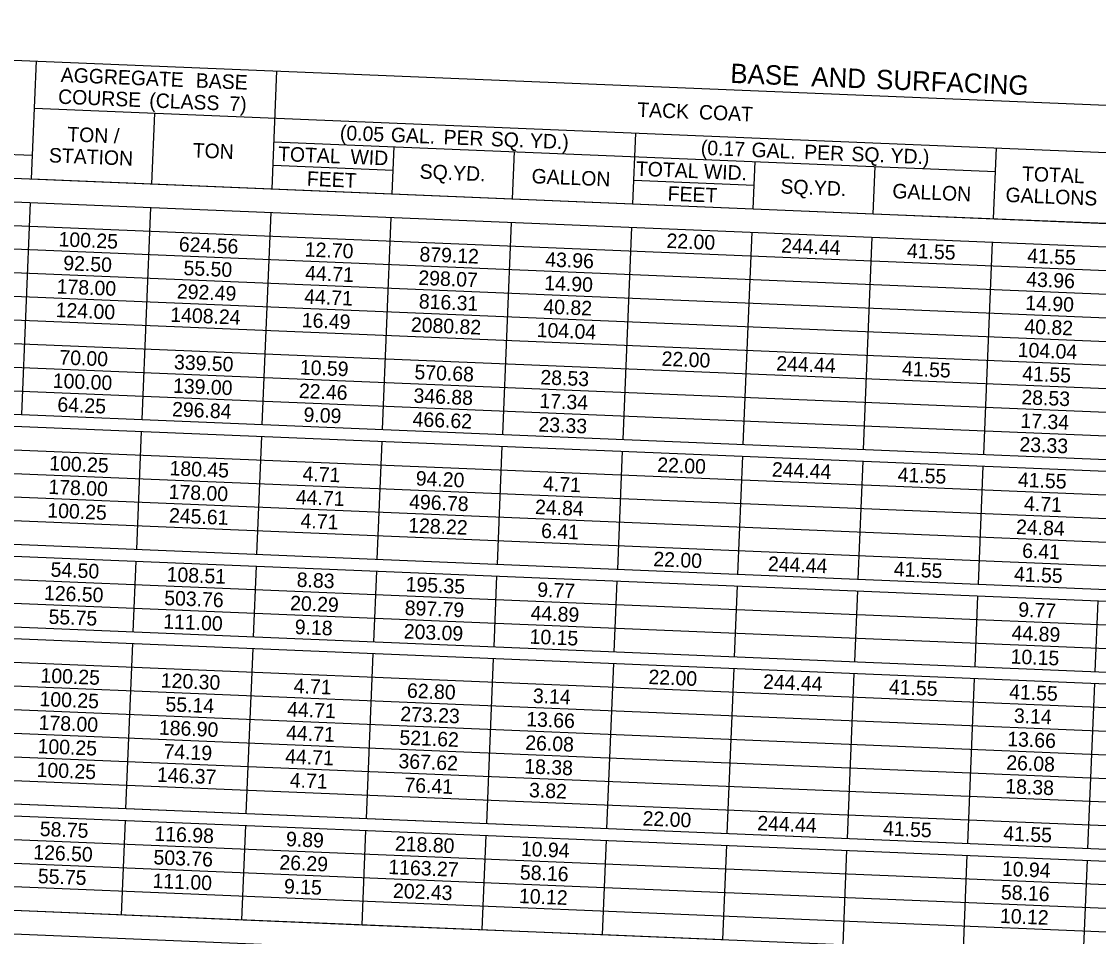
# Model space of a CAD drawing. Extents: x 1164179 to 1171425, y 1655958 to 1657208.
# Drawn here: x 1168414.3 to 1168859.2, y 1656454.9 to 1656832.9 of the extents above; entities that cross this region are included whole.
import ezdxf

# ---------------------------------------------------------------- set-up
doc = ezdxf.new("R2010")
doc.units = 0
doc.layers.add('Default', color=7, linetype='Continuous')

msp = doc.modelspace()

# ---------------------------------------------------------------- linework, layer by layer
at = {"layer": 'Default'}
for p, q in [((1168026.37, 1656832.93), (1169513.44, 1656771.41)), ((1168418.41, 1656767.92), (1168420.42, 1656816.63)), ((1168517.77, 1656763.81), (1168519.79, 1656812.52)), ((1168419.62, 1656797.14), (1169512.63, 1656751.93)), ((1168468.09, 1656765.86), (1168469.3, 1656795.09)), ((1168666.82, 1656757.64), (1168668.03, 1656786.87)), ((1168024.36, 1656784.22), (1169511.42, 1656722.7)), ((1168518.58, 1656783.29), (1168816.68, 1656770.96)), ((1168567.46, 1656761.75), (1168568.26, 1656781.24)), ((1168815.87, 1656751.48), (1168817.08, 1656780.7)), ((1168369.13, 1656779.72), (1168418.81, 1656777.66)), ((1168418.41, 1656767.92), (1168418.81, 1656777.66)), ((1168617.14, 1656759.7), (1168617.95, 1656779.18)), ((1168023.96, 1656774.48), (1169511.02, 1656712.96)), ((1168518.18, 1656773.55), (1168567.86, 1656771.49)), ((1168567.46, 1656761.75), (1168567.86, 1656771.49)), ((1168716.5, 1656755.59), (1168717.31, 1656775.07)), ((1168766.19, 1656753.53), (1168766.99, 1656773.01)), ((1168418.41, 1656767.92), (1168567.46, 1656761.75)), ((1168667.22, 1656767.38), (1168716.91, 1656765.33)), ((1168023.55, 1656764.74), (1169510.62, 1656703.22)), ((1168716.5, 1656755.59), (1168716.91, 1656765.33)), ((1168414.38, 1656670.5), (1168418.01, 1656758.18)), ((1168414.38, 1656670.5), (1168418.01, 1656758.18)), ((1168567.46, 1656761.75), (1168716.5, 1656755.59)), ((1168023.15, 1656754.99), (1169510.22, 1656693.48)), ((1168464.06, 1656668.45), (1168467.69, 1656756.12)), ((1168464.06, 1656668.45), (1168467.69, 1656756.12)), ((1168513.74, 1656666.39), (1168517.37, 1656754.07)), ((1168513.74, 1656666.39), (1168517.37, 1656754.07)), ((1168716.5, 1656755.59), (1168766.19, 1656753.53)), ((1168766.19, 1656753.53), (1168915.23, 1656747.37)), ((1168563.43, 1656664.34), (1168567.05, 1656752.01)), ((1168563.43, 1656664.34), (1168567.05, 1656752.01)), ((1168613.11, 1656662.28), (1168616.74, 1656749.96)), ((1168613.11, 1656662.28), (1168616.74, 1656749.96)), ((1168022.75, 1656745.25), (1169509.81, 1656683.74)), ((1168662.79, 1656660.23), (1168666.42, 1656747.9)), ((1168662.79, 1656660.23), (1168666.42, 1656747.9)), ((1168712.47, 1656658.17), (1168716.1, 1656745.84)), ((1168712.47, 1656658.17), (1168716.1, 1656745.84)), ((1168762.16, 1656656.11), (1168765.78, 1656743.79)), ((1168762.16, 1656656.11), (1168765.78, 1656743.79)), ((1168811.84, 1656654.06), (1168815.47, 1656741.73)), ((1168811.84, 1656654.06), (1168815.47, 1656741.73)), ((1168022.34, 1656735.51), (1169509.41, 1656673.99)), ((1168021.94, 1656725.77), (1169509.01, 1656664.25)), ((1168021.54, 1656716.03), (1169508.6, 1656654.51)), ((1168021.13, 1656706.29), (1169508.2, 1656644.77)), ((1168020.73, 1656696.54), (1169507.8, 1656635.03)), ((1168020.33, 1656686.8), (1169507.39, 1656625.29)), ((1168020.33, 1656686.8), (1169507.39, 1656625.29)), ((1168020.13, 1656681.93), (1169507.19, 1656620.41)), ((1168019.72, 1656672.19), (1169506.79, 1656610.67)), ((1168019.32, 1656662.45), (1169506.39, 1656600.93)), ((1168461.85, 1656614.87), (1168463.86, 1656663.58)), ((1168461.85, 1656614.87), (1168463.86, 1656663.58)), ((1168511.53, 1656612.81), (1168513.54, 1656661.52)), ((1168511.53, 1656612.81), (1168513.54, 1656661.52)), ((1168561.21, 1656610.76), (1168563.23, 1656659.46)), ((1168561.21, 1656610.76), (1168563.23, 1656659.46)), ((1168610.89, 1656608.7), (1168612.91, 1656657.41)), ((1168610.89, 1656608.7), (1168612.91, 1656657.41)), ((1168018.92, 1656652.71), (1169505.98, 1656591.19)), ((1168660.58, 1656606.65), (1168662.59, 1656655.35)), ((1168660.58, 1656606.65), (1168662.59, 1656655.35)), ((1168710.26, 1656604.59), (1168712.27, 1656653.3)), ((1168710.26, 1656604.59), (1168712.27, 1656653.3)), ((1168759.94, 1656602.54), (1168761.96, 1656651.24)), ((1168759.94, 1656602.54), (1168761.96, 1656651.24)), ((1168809.62, 1656600.48), (1168811.64, 1656649.19)), ((1168809.62, 1656600.48), (1168811.64, 1656649.19)), ((1168018.52, 1656642.97), (1169505.58, 1656581.45)), ((1168018.11, 1656633.22), (1169505.18, 1656571.71)), ((1168017.91, 1656628.35), (1169504.98, 1656566.84)), ((1168017.51, 1656618.61), (1169504.57, 1656557.09)), ((1168362.48, 1656618.98), (1169505.18, 1656571.71)), ((1168017.11, 1656608.87), (1169504.17, 1656547.35)), ((1168460.43, 1656580.77), (1168461.64, 1656610)), ((1168460.43, 1656580.77), (1168461.64, 1656610)), ((1168510.12, 1656578.72), (1168511.33, 1656607.94)), ((1168510.12, 1656578.72), (1168511.33, 1656607.94)), ((1168559.8, 1656576.66), (1168561.01, 1656605.89)), ((1168559.8, 1656576.66), (1168561.01, 1656605.89)), ((1168609.48, 1656574.61), (1168610.69, 1656603.83)), ((1168609.48, 1656574.61), (1168610.69, 1656603.83)), ((1168016.7, 1656599.13), (1169503.77, 1656537.61)), ((1168659.17, 1656572.55), (1168660.37, 1656601.78)), ((1168659.17, 1656572.55), (1168660.37, 1656601.78)), ((1168708.85, 1656570.49), (1168710.06, 1656599.72)), ((1168708.85, 1656570.49), (1168710.06, 1656599.72)), ((1168016.5, 1656594.26), (1169503.57, 1656532.74)), ((1168758.53, 1656568.44), (1168759.74, 1656597.66)), ((1168758.53, 1656568.44), (1168759.74, 1656597.66)), ((1168808.21, 1656566.38), (1168809.42, 1656595.61)), ((1168808.21, 1656566.38), (1168809.42, 1656595.61)), ((1168857.9, 1656564.33), (1168859.1, 1656593.55)), ((1168857.9, 1656564.33), (1168859.1, 1656593.55)), ((1168016.1, 1656584.52), (1169503.16, 1656523)), ((1168361.07, 1656584.88), (1169503.77, 1656537.61)), ((1168457.41, 1656507.71), (1168460.23, 1656575.9)), ((1168457.41, 1656507.71), (1168460.23, 1656575.9)), ((1168015.69, 1656574.77), (1169502.76, 1656513.26)), ((1168507.1, 1656505.65), (1168509.92, 1656573.85)), ((1168507.1, 1656505.65), (1168509.92, 1656573.85)), ((1168556.78, 1656503.6), (1168559.6, 1656571.79)), ((1168556.78, 1656503.6), (1168559.6, 1656571.79)), ((1168606.46, 1656501.54), (1168609.28, 1656569.73)), ((1168606.46, 1656501.54), (1168609.28, 1656569.73)), ((1168656.14, 1656499.49), (1168658.96, 1656567.68)), ((1168656.14, 1656499.49), (1168658.96, 1656567.68)), ((1168015.29, 1656565.03), (1169502.36, 1656503.51)), ((1168705.83, 1656497.43), (1168708.65, 1656565.62)), ((1168705.83, 1656497.43), (1168708.65, 1656565.62)), ((1168755.51, 1656495.38), (1168758.33, 1656563.57)), ((1168755.51, 1656495.38), (1168758.33, 1656563.57)), ((1168805.19, 1656493.32), (1168808.01, 1656561.51)), ((1168805.19, 1656493.32), (1168808.01, 1656561.51)), ((1168854.87, 1656491.27), (1168857.69, 1656559.46)), ((1168854.87, 1656491.27), (1168857.69, 1656559.46)), ((1168014.89, 1656555.29), (1169501.95, 1656493.77)), ((1168014.49, 1656545.55), (1169501.55, 1656484.03)), ((1168014.08, 1656535.81), (1169501.15, 1656474.29)), ((1168013.68, 1656526.07), (1169500.75, 1656464.55)), ((1168013.48, 1656521.19), (1169500.54, 1656459.68)), ((1168013.08, 1656511.45), (1169500.14, 1656449.94)), ((1168358.05, 1656511.82), (1169500.75, 1656464.55)), ((1168012.67, 1656501.71), (1169499.74, 1656440.19)), ((1168455.6, 1656463.87), (1168457.21, 1656502.84)), ((1168455.6, 1656463.87), (1168457.21, 1656502.84)), ((1168505.28, 1656461.82), (1168506.89, 1656500.78)), ((1168505.28, 1656461.82), (1168506.89, 1656500.78)), ((1168554.96, 1656459.76), (1168556.58, 1656498.73)), ((1168554.96, 1656459.76), (1168556.58, 1656498.73)), ((1168604.65, 1656457.71), (1168606.26, 1656496.67)), ((1168604.65, 1656457.71), (1168606.26, 1656496.67)), ((1168012.27, 1656491.97), (1169499.33, 1656430.45)), ((1168654.33, 1656455.65), (1168655.94, 1656494.62)), ((1168654.33, 1656455.65), (1168655.94, 1656494.62)), ((1168704.01, 1656453.59), (1168705.62, 1656492.56)), ((1168704.01, 1656453.59), (1168705.62, 1656492.56)), ((1168753.69, 1656451.54), (1168755.31, 1656490.51)), ((1168753.69, 1656451.54), (1168755.31, 1656490.51)), ((1168803.38, 1656449.48), (1168804.99, 1656488.45)), ((1168803.38, 1656449.48), (1168804.99, 1656488.45)), ((1168011.87, 1656482.23), (1168554.96, 1656459.76)), ((1168011.87, 1656482.23), (1169498.93, 1656420.71)), ((1168853.06, 1656447.43), (1168854.67, 1656486.4)), ((1168853.06, 1656447.43), (1168854.67, 1656486.4)), ((1168011.46, 1656472.49), (1169498.53, 1656410.97)), ((1168554.96, 1656459.76), (1168654.33, 1656455.65)), ((1168654.33, 1656455.65), (1168704.01, 1656453.59))]:
    msp.add_line(p, q, dxfattribs=at)

# ---------------------------------------------------------------- texts
for s, height, p in [('AGGREGATE', 6, (1168430.39, 1656807.96)), (' BASE', 6, (1168483.96, 1656805.74)), ('BASE', 8, (1168707, 1656807.6)), (' AND', 8, (1168737.48, 1656806.34)), (' SURFACING', 8, (1168764.23, 1656805.23)), ('COURSE', 6, (1168429.3, 1656798.99)), (' (CLASS', 6, (1168464.73, 1656797.53)), (' 7)', 6, (1168497.82, 1656796.16)), ('TACK', 6, (1168668.58, 1656793.6)), (' COAT', 6, (1168691.84, 1656792.64)), ('TON', 6, (1168433.08, 1656783.45)), ('(0.05', 6, (1168545.72, 1656784.04)), (' GAL.', 6, (1168564.55, 1656783.27)), (' /', 6, (1168450.09, 1656782.75)), (' PER', 6, (1168586.31, 1656782.37)), (' SQ.', 6, (1168605.82, 1656781.56)), (' YD.)', 6, (1168622, 1656780.89)), ('STATION', 6, (1168425.5, 1656774.76)), ('TON', 6, (1168484.91, 1656776.8)), ('TOTAL', 6, (1168520.17, 1656775.34)), ('(0.17', 6, (1168694.83, 1656777.88)), (' GAL.', 6, (1168713.54, 1656777.1)), (' PER', 6, (1168735.3, 1656776.2)), (' SQ.', 6, (1168754.81, 1656775.4)), (' YD.)', 6, (1168770.99, 1656774.73)), (' WID', 6, (1168547.83, 1656774.2)), ('SQ.YD.', 6, (1168578.67, 1656768.04)), ('GALLON', 6, (1168624.91, 1656766.13)), ('TOTAL WID.', 6, (1168668.01, 1656769.23)), ('TOTAL', 6, (1168827.54, 1656767.13)), ('FEET', 6, (1168532.07, 1656765.09)), ('SQ.YD.', 6, (1168727.72, 1656761.88)), ('FEET', 6, (1168681.12, 1656758.93)), ('GALLON', 6, (1168773.96, 1656759.97)), ('GALLONS', 6, (1168820.73, 1656758.41)), ('100.25', 6, (1168429.48, 1656740.06)), ('22.00', 6, (1168680.66, 1656739.43)), ('624.56', 6, (1168479.19, 1656738.01)), ('12.70', 6, (1168531.21, 1656735.85)), ('244.44', 6, (1168728.02, 1656737.47)), ('41.55', 6, (1168779.99, 1656735.32)), ('92.50', 6, (1168431.44, 1656730.22)), ('879.12', 6, (1168578.59, 1656733.89)), ('43.96', 6, (1168630.56, 1656731.74)), ('41.55', 6, (1168829.67, 1656733.26)), ('55.50', 6, (1168481.12, 1656728.17)), ('44.71', 6, (1168531.38, 1656726.09)), ('298.07', 6, (1168578.15, 1656724.15)), ('14.90', 6, (1168630.17, 1656722)), ('43.96', 6, (1168829.29, 1656723.52)), ('178.00', 6, (1168428.71, 1656720.58)), ('292.49', 6, (1168478.38, 1656718.52)), ('44.71', 6, (1168530.97, 1656716.35)), ('816.31', 6, (1168578.33, 1656714.39)), ('40.82', 6, (1168629.79, 1656712.26)), ('14.90', 6, (1168828.9, 1656713.78)), ('124.00', 6, (1168428.31, 1656710.84)), ('1408.24', 6, (1168475.66, 1656708.88)), ('16.49', 6, (1168529.99, 1656706.63)), ('2080.82', 6, (1168575.05, 1656704.76)), ('40.82', 6, (1168828.52, 1656704.04)), ('104.04', 6, (1168627.04, 1656702.61)), ('104.04', 6, (1168825.77, 1656694.39)), ('70.00', 6, (1168429.83, 1656691.26)), ('22.00', 6, (1168678.65, 1656690.72)), ('339.50', 6, (1168477.18, 1656689.3)), ('10.59', 6, (1168529.18, 1656687.15)), ('244.44', 6, (1168726, 1656688.76)), ('41.55', 6, (1168777.98, 1656686.61)), ('100.00', 6, (1168427.1, 1656681.61)), ('570.68', 6, (1168576.53, 1656685.19)), ('28.53', 6, (1168628.55, 1656683.03)), ('41.55', 6, (1168827.66, 1656684.56)), ('139.00', 6, (1168476.78, 1656679.55)), ('22.46', 6, (1168528.78, 1656677.4)), ('346.88', 6, (1168576.13, 1656675.45)), ('17.34', 6, (1168628.16, 1656673.29)), ('28.53', 6, (1168827.28, 1656674.81)), ('64.25', 6, (1168428.99, 1656671.77)), ('296.84', 6, (1168476.38, 1656669.81)), ('9.09', 6, (1168530.7, 1656667.57)), ('466.62', 6, (1168575.76, 1656665.7)), ('23.33', 6, (1168627.74, 1656663.55)), ('17.34', 6, (1168826.89, 1656665.07)), ('23.33', 6, (1168826.47, 1656655.33)), ('100.25', 6, (1168425.65, 1656647.52)), ('180.45', 6, (1168475.34, 1656645.46)), ('22.00', 6, (1168676.83, 1656646.88)), ('4.71', 6, (1168530.28, 1656643.19)), ('94.20', 6, (1168577.06, 1656641.25)), ('244.44', 6, (1168724.19, 1656644.92)), ('41.55', 6, (1168776.16, 1656642.77)), ('178.00', 6, (1168425.29, 1656637.77)), ('4.71', 6, (1168629.64, 1656639.08)), ('41.55', 6, (1168825.85, 1656640.72)), ('178.00', 6, (1168474.97, 1656635.72)), ('44.71', 6, (1168527.55, 1656633.54)), ('100.25', 6, (1168424.85, 1656628.03)), ('496.78', 6, (1168574.32, 1656631.61)), ('24.84', 6, (1168626.35, 1656629.46)), ('4.71', 6, (1168828.37, 1656630.86)), ('245.61', 6, (1168475.13, 1656625.95)), ('4.71', 6, (1168529.47, 1656623.7)), ('128.22', 6, (1168573.95, 1656621.86)), ('6.41', 6, (1168628.84, 1656619.59)), ('24.84', 6, (1168825.08, 1656621.23)), ('6.41', 6, (1168827.57, 1656611.37)), ('22.00', 6, (1168675.22, 1656607.92)), ('244.44', 6, (1168722.58, 1656605.96)), ('54.50', 6, (1168426.2, 1656603.58)), ('108.51', 6, (1168474.13, 1656601.6)), ('41.55', 6, (1168774.55, 1656603.81)), ('41.55', 6, (1168824.23, 1656601.75)), ('8.83', 6, (1168527.88, 1656599.37)), ('195.35', 6, (1168572.89, 1656597.51)), ('126.50', 6, (1168423.47, 1656593.94)), ('503.76', 6, (1168473.14, 1656591.88)), ('9.77', 6, (1168627.25, 1656595.26)), ('20.29', 6, (1168525.15, 1656589.73)), ('897.79', 6, (1168572.5, 1656587.77)), ('55.75', 6, (1168425.36, 1656584.1)), ('44.89', 6, (1168624.51, 1656585.62)), ('9.77', 6, (1168825.98, 1656587.04)), ('111.00', 6, (1168472.75, 1656582.14)), ('9.18', 6, (1168527.07, 1656579.89)), ('203.09', 6, (1168572.1, 1656578.03)), ('10.15', 6, (1168624.09, 1656575.88)), ('44.89', 6, (1168823.24, 1656577.4)), ('10.15', 6, (1168822.82, 1656567.66)), ('100.25', 6, (1168422.03, 1656559.84)), ('120.30', 6, (1168471.74, 1656557.78)), ('22.00', 6, (1168673.21, 1656559.21)), ('244.44', 6, (1168720.56, 1656557.25)), ('4.71', 6, (1168526.65, 1656555.51)), ('62.80', 6, (1168573.44, 1656553.58)), ('41.55', 6, (1168772.54, 1656555.1)), ('41.55', 6, (1168822.22, 1656553.04)), ('100.25', 6, (1168421.62, 1656550.1)), ('55.14', 6, (1168473.67, 1656547.95)), ('3.14', 6, (1168625.45, 1656551.43)), ('44.71', 6, (1168523.92, 1656545.87)), ('273.23', 6, (1168570.69, 1656543.93)), ('3.14', 6, (1168824.18, 1656543.2)), ('178.00', 6, (1168421.26, 1656540.36)), ('13.66', 6, (1168622.71, 1656541.78)), ('186.90', 6, (1168470.94, 1656538.3)), ('44.71', 6, (1168523.52, 1656536.13)), ('521.62', 6, (1168570.32, 1656534.19)), ('100.25', 6, (1168420.82, 1656530.62)), ('26.08', 6, (1168622.3, 1656532.04)), ('13.66', 6, (1168821.44, 1656533.56)), ('74.19', 6, (1168472.85, 1656528.46)), ('44.71', 6, (1168523.11, 1656526.38)), ('100.25', 6, (1168420.42, 1656520.87)), ('367.62', 6, (1168569.92, 1656524.45)), ('18.38', 6, (1168621.89, 1656522.3)), ('26.08', 6, (1168821.03, 1656523.82)), ('146.37', 6, (1168470.12, 1656518.82)), ('4.71', 6, (1168525.04, 1656516.55)), ('76.41', 6, (1168572.39, 1656514.59)), ('3.82', 6, (1168623.86, 1656512.46)), ('18.38', 6, (1168820.62, 1656514.08)), ('22.00', 6, (1168670.79, 1656500.76)), ('244.44', 6, (1168718.14, 1656498.8)), ('58.75', 6, (1168421.74, 1656496.42)), ('116.98', 6, (1168469.11, 1656494.46)), ('41.55', 6, (1168770.12, 1656496.65)), ('41.55', 6, (1168819.8, 1656494.59)), ('9.89', 6, (1168523.45, 1656492.22)), ('218.80', 6, (1168568.49, 1656490.35)), ('126.50', 6, (1168419.04, 1656486.78)), ('10.94', 6, (1168620.5, 1656488.2)), ('503.76', 6, (1168468.71, 1656484.72)), ('26.29', 6, (1168520.72, 1656482.57)), ('1163.27', 6, (1168565.75, 1656480.71)), ('55.75', 6, (1168420.93, 1656476.94)), ('58.16', 6, (1168620.09, 1656478.46)), ('10.94', 6, (1168819.23, 1656479.98)), ('111.00', 6, (1168468.32, 1656474.98)), ('9.15', 6, (1168522.62, 1656472.73)), ('202.43', 6, (1168567.67, 1656470.87)), ('10.12', 6, (1168619.71, 1656468.72)), ('58.16', 6, (1168818.82, 1656470.24)), ('10.12', 6, (1168818.44, 1656460.5))]:
    msp.add_text(s, height=height, rotation=357.6311, dxfattribs=at).set_placement(p)

doc.saveas('drawing.dxf')
